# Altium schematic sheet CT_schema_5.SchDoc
size 300 x 247 mm
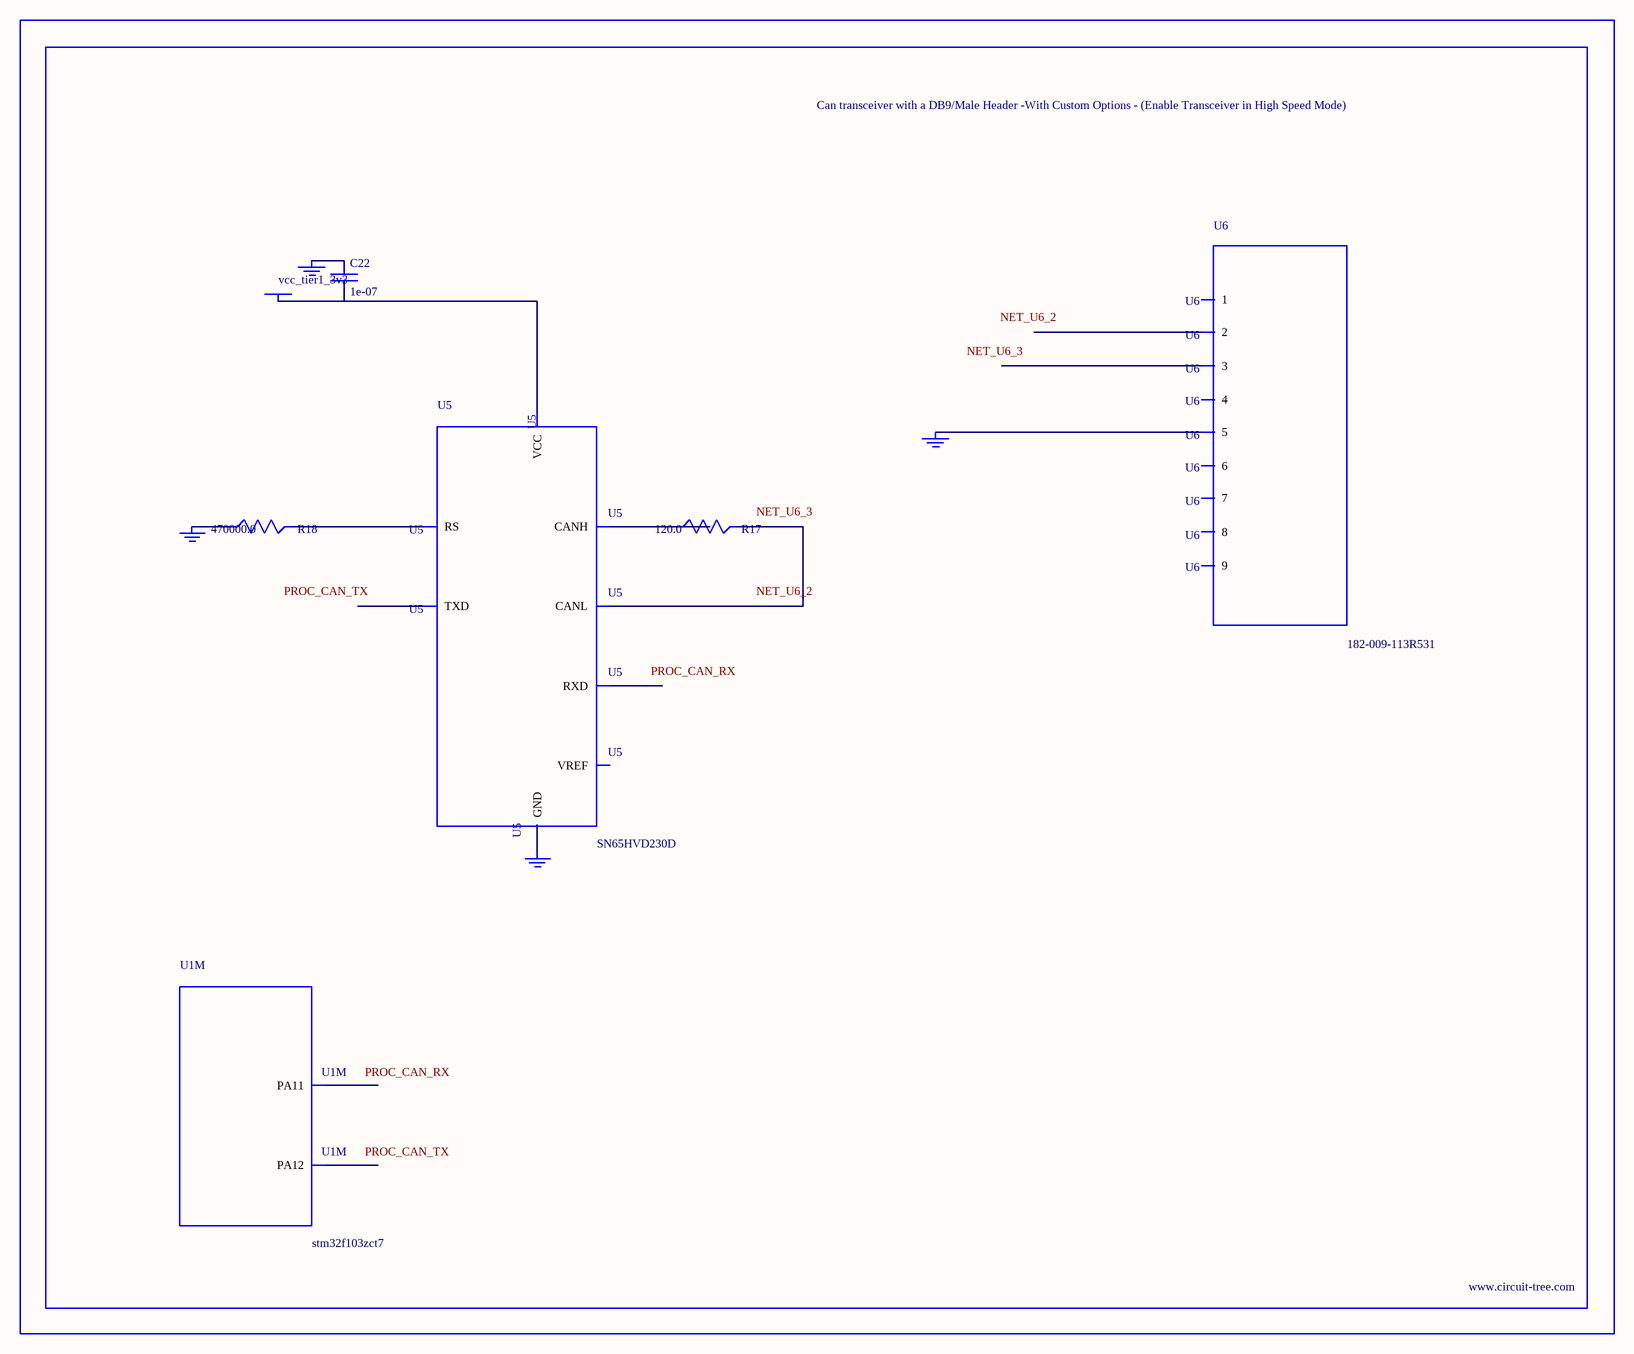
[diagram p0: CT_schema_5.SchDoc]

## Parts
BORDER4  (no value)
C22  1e-07  [C0402]
GND_INSTANCE_4_0  (no value)
GND_INSTANCE_4_1  (no value)
GND_INSTANCE_4_2  (no value)
GND_INSTANCE_4_3  (no value)
POWER_INSTANCE_4_0  vcc_tier1_3v3
R17  120.0  [R0603]
R18  470000.0  [R0603]
U1  stm32f103zct7  [LQFP144]  (part M of 13)
U5  SN65HVD230D  [SOIC-8]
U6  182-009-113R531  [182-009-MALE]

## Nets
NetC22_1: C22.1 GND_INSTANCE_4_0.0(GND)
NetC22_2: C22.2 POWER_INSTANCE_4_0.0(PWR) U5.3(VCC)
NetGND_INSTANCE_4_1_0: GND_INSTANCE_4_1.0(GND) R18.1
NetGND_INSTANCE_4_2_0: GND_INSTANCE_4_2.0(GND) U5.2(GND)
NetGND_INSTANCE_4_3_0: GND_INSTANCE_4_3.0(GND) U6.5
NetR17_1: R17.1 U5.7(CANH)
NetR17_2: R17.2 U5.6(CANL)
NetR18_2: R18.2 U5.8(RS)

Not connected (* = marked no-connect by the designer): U1 103(PA11) 104(PA12); U5 1(TXD) 4(RXD) 5(VREF); U6 1 2 3 4 6 7 8 9

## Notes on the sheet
- Labels drawn without touching a wire or pin: NET_U6_2, NET_U6_3, PROC_CAN_RX, PROC_CAN_TX

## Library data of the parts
BORDER4 = BORDER_PAGE4
C22 = C0402C104K3RACTU
GND_INSTANCE_4_0-GND_INSTANCE_4_3 = GND
POWER_INSTANCE_4_0 = PWR
R17 = RC0603JR-07120RL
R18 = RC0603JR-07470KL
